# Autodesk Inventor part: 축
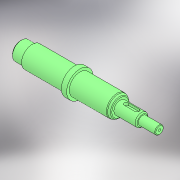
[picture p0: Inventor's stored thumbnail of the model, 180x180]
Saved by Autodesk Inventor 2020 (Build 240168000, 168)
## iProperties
Created: 2024-11
Part Number: 축
Material: 강철, 탄소
Document SubType Name: Modeling
Designer: 1강의실14
Density: 7.85 g/cm^3
Appearance: 기본값
Author: jhkim
Sending System: Autodesk Inventor 2025
Preprocessor: ST-DEVELOPER v20
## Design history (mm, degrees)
feature "솔리드1"
node "솔리드2"
